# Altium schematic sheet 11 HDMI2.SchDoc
size 297 x 209 mm
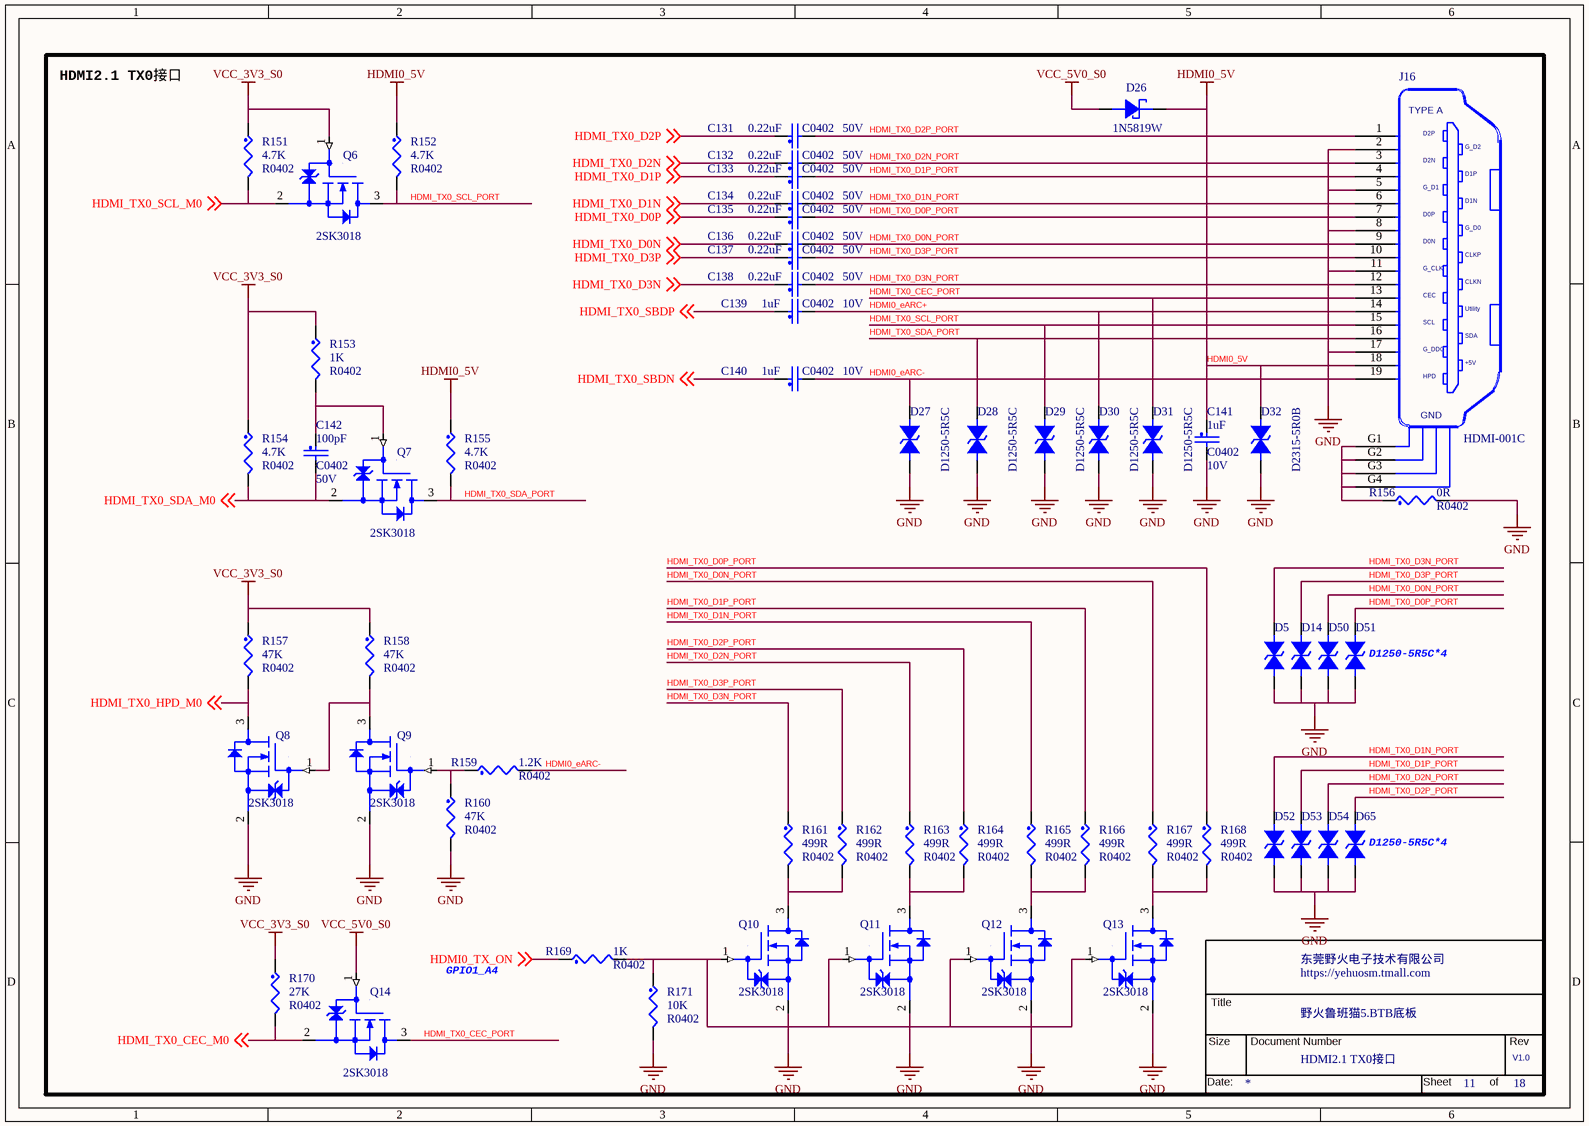
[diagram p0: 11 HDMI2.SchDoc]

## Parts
*  Doc: HDMI2.1 TX0接口  RevCode: V1.0  Title: 野火鲁班猫5.BTB底板  OrgName: 东莞野火电子技术有限公司  Page Number: 11  Page Count: 18  (hidden comment: TitleBlock_YHSCH)  (graphical)
C131  0.22uF  Voltage: 50V  [C0402]
C132  0.22uF  Voltage: 50V  [C0402]
C133  0.22uF  Voltage: 50V  [C0402]
C134  0.22uF  Voltage: 50V  [C0402]
C135  0.22uF  Voltage: 50V  [C0402]
C136  0.22uF  Voltage: 50V  [C0402]
C137  0.22uF  Voltage: 50V  [C0402]
C138  0.22uF  Voltage: 50V  [C0402]
C139  1uF  Voltage: 10V  [C0402]
C140  1uF  Voltage: 10V  [C0402]
C141  1uF  Voltage: 10V  [C0402]
C142  100pF  Voltage: 50V  [C0402]
D5  D1250-5R5C  [D0603/SMD]  (value not drawn)
D14  D1250-5R5C  [D0603/SMD]  (value not drawn)
D26  1N5819W  [SOD-123]
D27  D1250-5R5C  [D0603/SMD]
D28  D1250-5R5C  [D0603/SMD]
D29  D1250-5R5C  [D0603/SMD]
D30  D1250-5R5C  [D0603/SMD]
D31  D1250-5R5C  [D0603/SMD]
D32  D2315-5R0B  [D0603/SMD]
D50  D1250-5R5C  [D0603/SMD]  (value not drawn)
D51  D1250-5R5C  [D0603/SMD]  (value not drawn)
D52  D1250-5R5C  [D0603/SMD]  (value not drawn)
D53  D1250-5R5C  [D0603/SMD]  (value not drawn)
D54  D1250-5R5C  [D0603/SMD]  (value not drawn)
D65  D1250-5R5C  [D0603/SMD]  (value not drawn)
J16  HDMI-001C  [HDMI-SMD]
Q6  2SK3018  [SOT23]
Q7  2SK3018  [SOT23]
Q8  2SK3018  [SOT23]
Q9  2SK3018  [SOT23]
Q10  2SK3018  [SOT23]
Q11  2SK3018  [SOT23]
Q12  2SK3018  [SOT23]
Q13  2SK3018  [SOT23]
Q14  2SK3018  [SOT23]
R151  4.7K  [R0402]
R152  4.7K  [R0402]
R153  1K  [R0402]
R154  4.7K  [R0402]
R155  4.7K  [R0402]
R156  0R  [R0402]
R157  47K  [R0402]
R158  47K  [R0402]
R159  1.2K  [R0402]
R160  47K  [R0402]
R161  499R  [R0402]
R162  499R  [R0402]
R163  499R  [R0402]
R164  499R  [R0402]
R165  499R  [R0402]
R166  499R  [R0402]
R167  499R  [R0402]
R168  499R  [R0402]
R169  1K  [R0402]
R170  27K  [R0402]
R171  10K  [R0402]

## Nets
GND: C141.2 D5.1 D14.1 D27.1 D28.1 D29.1 D30.1 D31.1 D32.1 D50.1 D51.1 D52.1 D53.1 D54.1 D65.1 J16.2 J16.5 J16.8 J16.11 J16.17 Q8.2(SOURCE) Q9.2(SOURCE) Q10.2(SOURCE) Q11.2(SOURCE) Q12.2(SOURCE) Q13.2(SOURCE) R156.2 R160.2 R171.2
HDMI0_5V: C141.1 D26.1 D32.2 J16.18 R152.1 R155.1
VCC_3V3_S0: Q6.1(GATE) R151.1 R153.1 R154.1 R157.1 R158.1 R170.1
VCC_5V0_S0: D26.2 Q14.1(GATE)
HDMI0_eARC+: C139.2 D30.2 J16.14
HDMI0_eARC-: C140.2 D27.2 J16.19 R159.2
HDMI0_TX_ON: R169.1 ; off-sheet HDMI0_TX_ON
HDMI_TX0_CEC_M0: Q14.2(SOURCE) R170.2 ; off-sheet HDMI_TX0_CEC_M0
HDMI_TX0_CEC_PORT: D31.2 J16.13 Q14.3(DRAIN)
HDMI_TX0_D0N: C136.1 ; off-sheet HDMI_TX0_D0N
HDMI_TX0_D0N_PORT: C136.2 D50.2 J16.9 R167.1
HDMI_TX0_D0P: C135.1 ; off-sheet HDMI_TX0_D0P
HDMI_TX0_D0P_PORT: C135.2 D51.2 J16.7 R168.1
HDMI_TX0_D1N: C134.1 ; off-sheet HDMI_TX0_D1N
HDMI_TX0_D1N_PORT: C134.2 D52.2 J16.6 R165.1
HDMI_TX0_D1P: C133.1 ; off-sheet HDMI_TX0_D1P
HDMI_TX0_D1P_PORT: C133.2 D53.2 J16.4 R166.1
HDMI_TX0_D2N: C132.1 ; off-sheet HDMI_TX0_D2N
HDMI_TX0_D2N_PORT: C132.2 D54.2 J16.3 R163.1
HDMI_TX0_D2P: C131.1 ; off-sheet HDMI_TX0_D2P
HDMI_TX0_D2P_PORT: C131.2 D65.2 J16.1 R164.1
HDMI_TX0_D3N: C138.1 ; off-sheet HDMI_TX0_D3N
HDMI_TX0_D3N_PORT: C138.2 D5.2 J16.12 R161.1
HDMI_TX0_D3P: C137.1 ; off-sheet HDMI_TX0_D3P
HDMI_TX0_D3P_PORT: C137.2 D14.2 J16.10 R162.1
HDMI_TX0_HPD_M0: Q8.3(DRAIN) R157.2 ; off-sheet HDMI_TX0_HPD_M0
HDMI_TX0_SBDN: C140.1 ; off-sheet HDMI_TX0_SBDN
HDMI_TX0_SBDP: C139.1 ; off-sheet HDMI_TX0_SBDP
HDMI_TX0_SCL_M0: Q6.2(SOURCE) R151.2 ; off-sheet HDMI_TX0_SCL_M0
HDMI_TX0_SCL_PORT: D29.2 J16.15 Q6.3(DRAIN) R152.2
HDMI_TX0_SDA_M0: C142.2 Q7.2(SOURCE) R154.2 ; off-sheet HDMI_TX0_SDA_M0
HDMI_TX0_SDA_PORT: D28.2 J16.16 Q7.3(DRAIN) R155.2
NetC142_1: C142.1 Q7.1(GATE) R153.2
NetJ16_G1: J16.G1 J16.G2 J16.G3 J16.G4 R156.1
NetQ8_1: Q8.1(GATE) Q9.3(DRAIN) R158.2
NetQ9_1: Q9.1(GATE) R159.1 R160.1
NetQ10_1: Q10.1(GATE) Q11.1(GATE) Q12.1(GATE) Q13.1(GATE) R169.2 R171.1
NetQ10_3: Q10.3(DRAIN) R161.2 R162.2
NetQ11_3: Q11.3(DRAIN) R163.2 R164.2
NetQ12_3: Q12.3(DRAIN) R165.2 R166.2
NetQ13_3: Q13.3(DRAIN) R167.2 R168.2

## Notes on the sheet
- HDMI2.1 TX0接口
- (near D51) D1250-5R5C*4
- (near D65) D1250-5R5C*4
- (near Q14) GPIO1_A4

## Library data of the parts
* = TitleBlock_YHSCH: Cage Code: 1
C131-C138 = CAP_NP: CLASS: DISCRETE; 生命周期: 量产; 价格: 0.074942; 规格书: 太诱-贴片电容.pdf; 类别: 贴片电容0402; 品牌: 太诱; 条码: EBF29060266; 规格编号: UMK105BJ224MV-F; 规格: 贴片电容0.22uF 20% 50V X5R 0402
C139-C141 = CAP_NP: CLASS: DISCRETE; 生命周期: 量产; 价格: 0.01191; 规格书: 风华电容.pdf; 类别: 贴片电容0402; 品牌: 风华; 条码: EBF29060121; 规格编号: 0402X105K100NT; 规格: 贴片电容1uF 10% 10V X5R 0402
C142 = CAP_NP: CLASS: DISCRETE; 生命周期: 量产; 价格: 0.034837; 规格书: 村田040系列贴片电容.pdf; 类别: 贴片电容0402; 品牌: 村田; 条码: EBF29060302; 规格编号: GRT1555C1H101JA; 规格: 贴片电容100pF 5% 50V C0G 0402
D5 D14 D27-D31 D50-D54 D65 = DIODE BI-DIR TRIG: PCB Footprint: R0201; 备注: 应用于HDMI2.1; 生命周期: 量产; 规格书: 千虹_D1250-5R5C.pdf; 类别: 贴片ESD; 品牌: 千虹; 条码: EBFCIS240604160037; 规格: 防静电保护ESD二极管 反向工作电压5.5V 击穿电压6V 钳位电压10.5V 结电容Cj 0.17pF
D26 = DIODE_SCHTKY: CLASS: IC; 规格: 肖特基二极管 直流反向耐压40V 平均整流电流1A 正向压降0.6V@1A SOD-123; 条码: EBF29140016; 品牌: 台湾迪嘉; 类别: 贴片肖特基二极管; 规格书: 1N5819W.pdf; 价格: 0.175675; 生命周期: 量产; 丝印: SL
D32 = DIODE BI-DIR TRIG: PCB Footprint: esd0402; 备注: 通用; 生命周期: 量产; 规格书: 千虹_D2315-5R0B.pdf; 类别: 贴片ESD; 品牌: 千虹; 条码: EBFCIS240517170922; 规格: 防静电保护ESD二极管 反向工作电压5V 击穿电压7V 钳位电压10.5V 结电容Cj 0.3pF
J16 = HDMI-001C: VPN: 1166-2C105-211; Vendor: Comtek; OriginalSymbolOrigin: (-200,650); CLASS: IO; 规格: HDMI立式; 条码: EBF29040081; 品牌: 讯普; 类别: HDMI连接器; 规格书: HDMI-001C.pdf; 生命周期: 量产
Q6 Q7 Q9 = 2SK3018: CLASS: IC; 规格: N沟道MOS 导通电阻8Ω 电流10mA 0.8V可驱动; 条码: EBF29280009; 品牌: 江苏长电; 类别: N-MOS; 规格书: 长电科技-2SK3018.pdf; 价格: 0.120725; 生命周期: 量产; 丝印: KN
Q8 Q10-Q14 = 2SK3018: CLASS: IC; 丝印: KN; 生命周期: 量产; 价格: 0.120725; 规格书: 长电科技-2SK3018.pdf; 类别: N-MOS; 品牌: 江苏长电; 条码: EBF29280009; 规格: N沟道MOS 导通电阻8Ω 电流10mA 0.8V可驱动
R151 R152 R154 R155 = RES: CLASS: DISCRETE; 生命周期: 量产; 规格书: 合科泰-RI系列电阻.pdf; 类别: 贴片电阻0402; 品牌: 合科泰; 条码: EBF29070047; 规格编号: RI0402L4701FT; 规格: 贴片电阻4.7K 1% 1/16W 0402
R153 R169 = RES: CLASS: DISCRETE; 生命周期: 量产; 规格书: 合科泰-RI系列电阻.pdf; 类别: 贴片电阻0402; 品牌: 合科泰; 条码: EBF29070050; 规格编号: RI0402L1001FT; 规格: 贴片电阻1K 1% 1/16W 0402
R156 = RES: CLASS: DISCRETE; 规格: 贴片电阻0R 1% 1/16W 0402; 规格编号: RI0402L000FT; 条码: EBF29070049; 品牌: 合科泰; 类别: 贴片电阻0402; 规格书: 合科泰-RI系列电阻.pdf; 生命周期: 量产
R157 R158 = RES: CLASS: DISCRETE; 生命周期: 量产; 规格书: 厚声-无铅厚膜电阻.pdf; 类别: 贴片电阻0402; 品牌: 厚声; 条码: EBF29070247; 规格编号: 0402WGF4702TCE; 规格: 贴片电阻47K 1% 1/16W 0402
R159 = RES: CLASS: DISCRETE; 生命周期: 量产; 价格: 0.001447; 规格书: 厚声-无铅厚膜电阻.pdf; 类别: 贴片电阻0402; 品牌: 厚声; 条码: EBFCIS221112112140; 规格编号: 0402WGF1201TCE; 规格: 贴片电阻1.2K 1% 1/16W 0402
R160 = RES: CLASS: DISCRETE; 规格: 贴片电阻47K 1% 1/16W 0402; 规格编号: 0402WGF4702TCE; 条码: EBF29070247; 品牌: 厚声; 类别: 贴片电阻0402; 规格书: 厚声-无铅厚膜电阻.pdf; 生命周期: 量产
R161 R163 R166 R168 = RES: CLASS: DISCRETE; 生命周期: 量产; 价格: 0.003791; 规格书: 厚声-无铅厚膜电阻.pdf; 类别: 贴片电阻0402; 品牌: 厚声; 条码: EBF29070287; 规格编号: 0402WGF4990TCE; 规格: 贴片电阻499R 1% 1/16W 0402
R162 R164 R165 R167 = RES: CLASS: DISCRETE; 规格: 贴片电阻499R 1% 1/16W 0402; 规格编号: 0402WGF4990TCE; 条码: EBF29070287; 品牌: 厚声; 类别: 贴片电阻0402; 规格书: 厚声-无铅厚膜电阻.pdf; 价格: 0.003791; 生命周期: 量产
R170 = RES: CLASS: DISCRETE; 生命周期: 量产; 价格: 0.007054; 规格书: YAGEO国巨厚膜无铅电阻.pdf; 类别: 贴片电阻0402; 品牌: 国巨; 条码: EBF29070003; 规格编号: AC0402FR-0727KL; 规格: 贴片电阻27K 1% 1/16W 0402
R171 = RES: CLASS: DISCRETE; 生命周期: 量产; 价格: 0.002773; 规格书: 厚声-无铅厚膜电阻.pdf; 类别: 贴片电阻0402; 品牌: 厚声; 条码: EBF29070046; 规格编号: 0402WGF1002TCE; 规格: 贴片电阻10K 1% 1/16W 0402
